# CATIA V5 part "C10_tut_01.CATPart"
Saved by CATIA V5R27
Part number: Part1
Bounding box of the stored display mesh (mm): x -88.598 to 88.598, y -88.598 to 152.301, z -258.54 to 20
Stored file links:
  E:\_Deepak\2017_Deepak\CATIA\Resources\Tutorial Files\Tutorials\c10_catia_v5_6r2016_tut\C10_tut_01.CATPart
  J.rX
  E:\ashutosh\Academics\Catia\CATIA V5-6R2013_partfiles\Tutorials\c10_catia_v5-6r2013_tut\c10tut1.CATPart
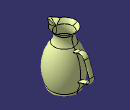
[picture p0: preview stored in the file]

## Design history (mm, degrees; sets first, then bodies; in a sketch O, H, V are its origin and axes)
Body1 (main body)
  Sketch1 on xy-plane, origin (0, 0, 0), H (1, 0, 0), V (0, 1, 0)
    circle A1 centre (0, 0) radius 45
    point P1 (-5, -44.7214)
    point P2 (5, -44.7214)
    distance P1 P2 = 10
    radius A1 = 45
    coincidence: P1 A1
    symmetry: P1 P2 V
  Plane1: type Offset, RefPlane xy-plane, Offset 20
  Sketch2 on Plane1, origin (0, 0, 20), H (1, 0, 0), V (0, 1, 0)
    arc A1 centre (0, 0) radius 60 from (30.5123, -51.6623) to (-30.5123, -51.6623) ccw
    arc A2 centre (0, -75) radius 10 from (-7.9335, -81.0876) to (7.9335, -81.0876) ccw
    point P1 (0, -75)
    line L1 (-7.9335, -81.0876) -> (-30.5123, -51.6623)
    point P2 (-7.9335, -81.0876)
    point P3 (-30.5123, -51.6623)
    point P4 (30.5123, -51.6623)
    point P5 (7.9335, -81.0876)
    line L2 (7.9335, -81.0876) -> (30.5123, -51.6623)
    radius A1 = 60
    radius A2 = 10
    distance O P1 = 75
    angle L1 L2 = 75
    coincidence: P1 V
    tangency: L1 A2
    symmetry: P3 P4 V, P2 P5 V, L1 L2 V
  Line1: type PtPt, FirstPoint vertex [element of Sketch2 | element of Sketch2], SecondPoint Sketch1.P2
  Loft1: Sections (Sketch1.A1; Sketch2), Guides Line1
  Sketch3 on yz-plane, origin (0, 0, 0), H (0, 1, 0), V (0, 0, 1)
    axis line L1 (0, 44.6071) -> (0, -361.7772)
    point P1 (0, 44.6071)
    arc A1 centre (96.9659, -18.0152) radius 55 from (45, 0) to (52.2225, -50) ccw
    point P4 (45, 0)
    point P5 (52.2225, -50)
    arc A2 centre (-106.3983, -163.4215) radius 195 from (52.2225, -50) to (70, -246.5398) cw
    point P7 (70, -246.5398)
    point P8 (54, -258.5398)
    arc A3 centre (0, -425) radius 175 from (54, -258.5398) to (0, -250) ccw
    point P9 (0, -425)
    point P10 (0, -250)
    line L2 (54, -258.5398) -> (64, -258.5398)
    arc A4 centre (64, -251.0398) radius 7.5 from (70, -246.5398) to (64, -258.5398) cw
    radius about axis P4 L1 = 45
    radius A1 = 55
    distance H P5 = 50
    radius A2 = 195
    radius about axis P7 L1 = 70
    distance H P10 = 250
    radius about axis P8 L1 = 54
    radius A3 = 175
    length L2 = 10
    radius A4 = 7.5
    coincidence: P1 V, P4 H, P10 L1, P9 V
    vertical: L1 V
    tangency: A1 A2, A4 L2
    horizontal: L2 H
  Revol1: Element1 Sketch3, Angle1 360
  Sketch4 on yz-plane, origin (0, 0, 0), H (0, 1, 0), V (0, 0, 1)
    point P1 (35.2741, -74.8693)
    line L1 (35.2741, -74.8693) -> (86.9572, -56.0582)
    line L2 (119, -71) -> (145.5066, -143.8262)
    line L3 (130.5647, -175.869) -> (63.8466, -200.1524)
    arc A1 centre (95.5077, -79.5505) radius 25 from (86.9572, -56.0582) to (119, -71) cw
    point P4 (119, -71)
    arc A2 centre (122.0142, -152.3767) radius 25 from (130.5647, -175.869) to (145.5066, -143.8262) ccw
    radius A1 = 25
    radius A2 = 25
    length L1 = 55
    distance H P4 = 71
    angle H L1 = 20
    distance P4 V = 119
    length L2 = 77.5
    length L3 = 71
    perpendicularity: L3 L2, L1 L2
    tangency: A1 L1, A1 L2, A2 L3, A2 L2
  Plane2: type Normal, Curve Sketch4, RefPoint Sketch4.P1, Ratio 0
  Sketch5 on Plane2, origin (0, 7.0853, 2.5788), H (1, 0, 0), V (0, -0.342, 0.9397)
    point P1 (0, -82.1273)
    ellipse A1 centre (0, -82.1273) semi-axes 12.5, 5 rotation 0
    point P2 (0, -87.1273)
    "Radius" A1 = 5
    "Radius" A1 = 12.5
    coincidence: P1 V, P2 V, A1 P2
  Sweep1: type Unspec, Profile Sketch5, Guide Sketch4
  Split1: ToCut Sweep1, Cutting Revol1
